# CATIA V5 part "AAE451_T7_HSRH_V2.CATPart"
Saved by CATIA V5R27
Part number: HSRH
Bounding box of the stored display mesh (mm): x -160.298 to 13.7, y -18.483 to 4.512, z -125 to 115
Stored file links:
  W:\AAE 451\AAE451_T7_TailAssembly_V2\AAE451_T7_HSRH_V2.CATPart
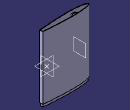
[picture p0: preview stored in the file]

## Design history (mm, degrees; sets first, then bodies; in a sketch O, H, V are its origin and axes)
Set1 "GeometryFromExcel"
  Point1: (1, 0.001, 0)
  Point2: (0.95, 0.0067, 0)
  Point3: (0.9, 0.0121, 0)
  Point4: (0.8, 0.0219, 0)
  Point5: (0.7, 0.0305, 0)
  Point6: (0.6, 0.038, 0)
  Point7: (0.5, 0.0441, 0)
  Point8: (0.4, 0.0484, 0)
  Point9: (0.3, 0.05, 0)
  Point10: (0.25, 0.0495, 0)
  Point11: (0.2, 0.0478, 0)
  Point12: (0.15, 0.0445, 0)
  Point13: (0.1, 0.039, 0)
  Point14: (0.075, 0.035, 0)
  Point15: (0.05, 0.0296, 0)
  Point16: (0.025, 0.0218, 0)
  Point17: (0.0125, 0.0158, 0)
  Point18: (0, 0, 0)
  Point19: (0.0125, -0.0158, 0)
  Point20: (0.025, -0.0218, 0)
  Point21: (0.05, -0.0296, 0)
  Point22: (0.075, -0.035, 0)
  Point23: (0.1, -0.039, 0)
  Point24: (0.15, -0.0445, 0)
  Point25: (0.2, -0.0478, 0)
  Point26: (0.25, -0.0495, 0)
  Point27: (0.3, -0.05, 0)
  Point28: (0.4, -0.0484, 0)
  Point29: (0.5, -0.0441, 0)
  Point30: (0.6, -0.038, 0)
  Point31: (0.7, -0.0305, 0)
  Point32: (0.8, -0.0219, 0)
  Point33: (0.9, -0.0121, 0)
  Point34: (0.95, -0.0067, 0)
  Point35: (1, -0.001, 0)
  Point36: (1, 0.001, 0)
  Point37: (0.95, 0.0067, 0)
  Point38: (0.9, 0.0121, 0)
  Point39: (0.8, 0.0219, 0)
  Point40: (0.7, 0.0305, 0)
  Point41: (0.6, 0.038, 0)
  Point42: (0.5, 0.0441, 0)
  Point43: (0.4, 0.0484, 0)
  Point44: (0.3, 0.05, 0)
  Point45: (0.25, 0.0495, 0)
  Point46: (0.2, 0.0478, 0)
  Point47: (0.15, 0.0445, 0)
  Point48: (0.1, 0.039, 0)
  Point49: (0.075, 0.035, 0)
  Point50: (0.05, 0.0296, 0)
  Point51: (0.025, 0.0218, 0)
  Point52: (0.0125, 0.0158, 0)
  Point53: (0, 0, 0)
  Point54: (0.0125, -0.0158, 0)
  Point55: (0.025, -0.0218, 0)
  Point56: (0.05, -0.0296, 0)
  Point57: (0.075, -0.035, 0)
  Point58: (0.1, -0.039, 0)
  Point59: (0.15, -0.0445, 0)
  Point60: (0.2, -0.0478, 0)
  Point61: (0.25, -0.0495, 0)
  Point62: (0.3, -0.05, 0)
  Point63: (0.4, -0.0484, 0)
  Point64: (0.5, -0.0441, 0)
  Point65: (0.6, -0.038, 0)
  Point66: (0.7, -0.0305, 0)
  Point67: (0.8, -0.0219, 0)
  Point68: (0.9, -0.0121, 0)
  Point69: (0.95, -0.0067, 0)
  Point70: (1, -0.001, 0)
  Curve1: Elements (Point36; Point37; Point38; Point39; Point40; Point41; Point42; Point43; Point44; Point45; Point46; Point47; Point48; Point49; Point50; Point51; Point52; Point53; Point54; Point55; Point56; Point57; Point58; Point59; Point60; Point61; Point62; Point63; Point64; Point65; Point66; Point67; Point68; Point69; Point70)
  Sketch1 on xy-plane, origin (0, 0, 0), H (1, 0, 0), V (0, 1, 0)
    projected curve E1 from edge of Curve1
    point P1 (1, 0.0011)
    line L1 (1, 0.0011) -> (1, -0.001)
    point P3 (1, 0.001)
    point P4 (1, -0.001)
    reference projected point E2 (1, 0.001) from Point1
    reference projected point E3 (1, -0.001) from Point35
    coincidence: P3 E2, P4 E3, P1 P3
Body1 (main body)
  Pad1: profile Sketch1, direction (0, 0, 1), length 1.5215, mirrored extent
  Scaling1: ToTransfor Pad1, Reference Point40, Ratio 230
  Sketch2 on zx-plane, origin (0, 0, 0), H (-1, 0, 0), V (0, 0, 1)
    line L1 (-74.5369, 349.945) -> (165.4631, 349.945)
    line L2 (165.4631, 349.945) -> (165.4631, 115)
    line L3 (165.4631, 115) -> (-74.5369, 115)
    line L4 (-74.5369, 115) -> (-74.5369, 349.945)
    line L5 (-74.5369, -115) -> (165.4631, -115)
    line L6 (165.4631, -115) -> (165.4631, -349.945)
    line L7 (165.4631, -349.945) -> (-74.5369, -349.945)
    line L8 (-74.5369, -349.945) -> (-74.5369, -115)
    reference projected line E1 (-69.7, 349.945) -> (160.3, 349.945) from edge [face of Pad1 from Sketch1.E1 | end face of Pad1]
    reference projected line E2 (-69.7, -349.945) -> (160.3, -349.945) from edge [start face of Pad1 | face of Pad1 from Sketch1.E1]
    distance L3 L5 = 230
    distance L2 L4 = 240
    horizontal: L1 H, L3 H, L5 H, L7 H
    vertical: L2 V, L4 V, L6 V, L8 V
    symmetry: L3 L5 H, L8 L4 H, L2 L6 H
    coincidence: L1 E1, L7 E2
  Pocket1: profile Sketch2, direction (0, -1, 0), through (limit type 6), opposite side through (limit type 6)
  Sketch3 on face of Pocket1 from Sketch2.L3, origin (0, 0, 115), H (1, 0, 0), V (0, 1, 0)
    line L1 (13.7, -12.9188) -> (13.7, -1.064)
    point P1 (13.7, -12.9188)
    point P2 (13.7, -1.064)
    reference projected curve E1 from edge [face of Pad1 from Sketch1.E1 | face of Pocket1 from Sketch2.L3]
    reference projected curve E2 from edge [face of Pad1 from Sketch1.E1 | face of Pocket1 from Sketch2.L3]
    projected curve E3 from edge [face of Pad1 from Sketch1.E1 | face of Pocket1 from Sketch2.L3]
    projected curve E4 from edge [face of Pad1 from Sketch1.E1 | face of Pocket1 from Sketch2.L3]
    projected curve E5 from edge [face of Pad1 from Sketch1.E1 | face of Pocket1 from Sketch2.L3]
    point P3 (69.7, -6.7499)
    line L2 (69.7, -6.7499) -> (69.7, -7.2329)
    distance L1 P3 = 56
    coincidence: P1 E1, P2 E2
    vertical: L1 V
  Pocket2: profile Sketch3, direction (0, 0, -1), through (limit type 6)
  Shell1: ExtOffset 0, Face (face of Pocket1 from Sketch2.L3; face of Pocket1 from Sketch2.L5), IntOffset 1.8
  Plane1: type Offset, RefPlane yz-plane, Offset 120, reversed
  Sketch4 on face of Pocket1 from Sketch2.L5, origin (0, 0, -115), H (1, 0, 0), V (0, -1, 0)
    projected curve E1 from edge [face of Shell1 | face of Pocket1 from Sketch2.L5]
    projected line E2 (11.9, 11.2688) -> (11.9, 2.714) from edge [face of Shell1 | face of Pocket1 from Sketch2.L5]
  Pad2: profile Sketch4, direction (0, 0, -1), length 10, opposite side length 10
  Sketch5 on end face of Pad2, origin (0, 0, -125), H (1, 0, 0), V (0, -1, 0)
    circle A1 centre (-110, 7) radius 6.85
    point P1 (-110, 7)
    reference intersected line E1 through (-120, 0) direction (0, 1) from Plane1
    distance E1 P1 = 10
    distance H P1 = 7
    radius A1 = 6.85
  Pocket3: profile Sketch5, direction (0, 0, 1), through (limit type 3)
  Sketch6 on face of Pocket1 from Sketch2.L5, origin (0, 0, -115), H (1, 0, 0), V (0, -1, 0)
    projected circle E1 centre (-110, 7) radius 6.85 from edge [end face of Pad2 | face of Pocket3 from Sketch5.A1]
    circle A1 centre (-110, 7) radius 10
    radius A1 = 10
    concentricity: A1 E1
  Pad3: profile Sketch6, direction (0, 0, 1), length 220
  Sketch7 on end face of Pad2, origin (0, 0, -125), H (1, 0, 0), V (0, -1, 0)
    circle A1 centre (-135, 6) radius 2.972
    point P1 (-135, 6)
    radius A1 = 2.972
    distance V P1 = 135
    distance H P1 = 6
  Pocket4: profile Sketch7, direction (0, 0, 1), length 7.92
  RectPattern1: of Pocket4, direction 1 instances 2, spacing 125, along end face of Pad2
  Sketch8 on face of Pocket2 from Sketch3.L1, origin (13.7, 0, 0), H (0, 1, 0), V (0, 0, 1)
    line L1 (-7.4914, 8) -> (-6.4914, 8)
    line L2 (-6.4914, 8) -> (-6.4914, -8)
    line L3 (-6.4914, -8) -> (-7.4914, -8)
    line L4 (-7.4914, -8) -> (-7.4914, 8)
    construction line L5 (-6.9914, 9.8282) -> (-6.9914, -16.3419)
    reference projected line E1 (-12.9188, 115) -> (-12.9188, -115) from edge [face of Pad1 from Sketch1.E1 | face of Pocket2 from Sketch3.L1]
    reference projected line E2 (-1.064, 115) -> (-1.064, -115) from edge [face of Pocket2 from Sketch3.L1 | face of Pad1 from Sketch1.E1]
    length L1 = 1
    length L2 = 16
    horizontal: L1 H, L3 H
    vertical: L2 V, L4 V
    symmetry: L4 L2 L5, E1 E2 L5, L1 L3 H
  Pocket5: profile Sketch8, direction (-1, 0, 0), length 13.7
  Sketch9 on face of Pocket2 from Sketch3.L1, origin (13.7, 0, 0), H (0, 1, 0), V (0, 0, 1)
    projected line E1 (-6.4914, -8) -> (-6.4914, 8) from edge [face of Pocket2 from Sketch3.L1 | face of Pocket5 from Sketch8.L2]
    projected line E2 (-7.4914, 8) -> (-7.4914, -8) from edge [face of Pocket2 from Sketch3.L1 | face of Pocket5 from Sketch8.L4]
    projected line E3 (-6.4914, 8) -> (-7.4914, 8) from edge [face of Pocket2 from Sketch3.L1 | face of Pocket5 from Sketch8.L1]
    projected line E4 (-7.4914, -8) -> (-6.4914, -8) from edge [face of Pocket2 from Sketch3.L1 | face of Pocket5 from Sketch8.L3]
    line L1 (-8.4914, 9) -> (-5.4914, 9)
    line L2 (-5.4914, 9) -> (-5.4914, -9)
    line L3 (-5.4914, -9) -> (-8.4914, -9)
    line L4 (-8.4914, -9) -> (-8.4914, 9)
    distance L4 E2 = 1
    distance E3 L1 = 1
    distance E1 L2 = 1
    distance L3 E4 = 1
    horizontal: L1 H, L3 H
    vertical: L2 V, L4 V
  Pad4: profile Sketch9, direction (-1, 0, 0), length 13.7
